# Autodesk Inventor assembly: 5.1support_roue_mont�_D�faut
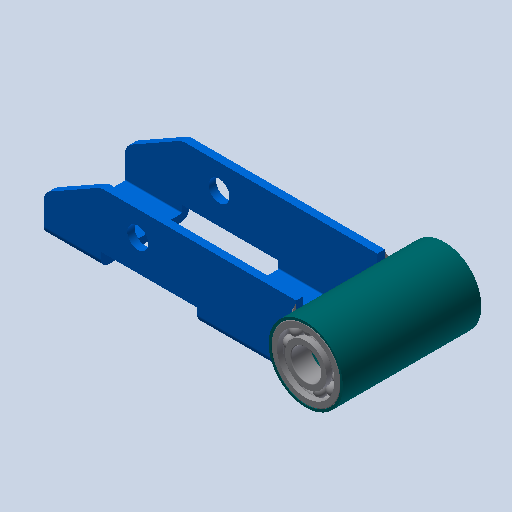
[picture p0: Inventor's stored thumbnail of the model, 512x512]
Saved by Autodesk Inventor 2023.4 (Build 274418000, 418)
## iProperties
Created: 2011-01
Part Number: 5.1support_roue_mont�_D�faut
Document SubType Name: Assembly
Designer: eric
Mass: 34.9166 g
Surface Area: 331.186 cm^2
Volume: 34.9166 cm^3
Density: 1 g/cm^3
Author: eric
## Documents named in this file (7)
- C:\Users\bruno\Documents\1-Cours-2024-25\TSsI\7-Dynamique\chariot de golf\chariot_de_golf\chariot_de_golf_trolem\5.1support_roue_monte_Defaut.iam
- C:\Users\bruno\Documents\1-Cours-2024-25\TSsI\7-Dynamique\chariot de golf\chariot_de_golf\chariot_de_golf_trolem\5.1tube_roulement_Defaut.ipt
- C:\Users\bruno\Documents\1-Cours-2024-25\TSsI\7-Dynamique\chariot de golf\chariot_de_golf\chariot_de_golf_trolem\5.1roulement_12x28x8_Defaut.iam
- C:\Users\bruno\Documents\1-Cours-2024-25\TSsI\7-Dynamique\chariot de golf\chariot_de_golf\chariot_de_golf_trolem\5.1support roulement_Defaut.ipt
- C:\Users\bruno\Documents\1-Cours-2024-25\TSsI\7-Dynamique\chariot de golf\chariot_de_golf\chariot_de_golf_trolem\bead102_Defaut.ipt
- C:\Users\bruno\Documents\1-Cours-2024-25\TSsI\7-Dynamique\chariot de golf\chariot_de_golf\chariot_de_golf_trolem\bead101_Defaut.ipt
- C:\Users\bruno\Documents\1-Cours-2024-25\TSsI\7-Dynamique\chariot de golf\chariot_de_golf\chariot_de_golf_trolem\bead100_Defaut.ipt
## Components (7 placed, 6 different names)
1. 5.1tube_roulement_Defaut:1
2. 5.1roulement_12x28x8_Defaut:1 [sub-assembly]
3. 5.1support roulement_Defaut:1
4. bead102_Defaut:1
5. bead101_Defaut:1
6. bead100_Defaut:1
7. 5.1roulement_12x28x8_Defaut:2 [sub-assembly]
